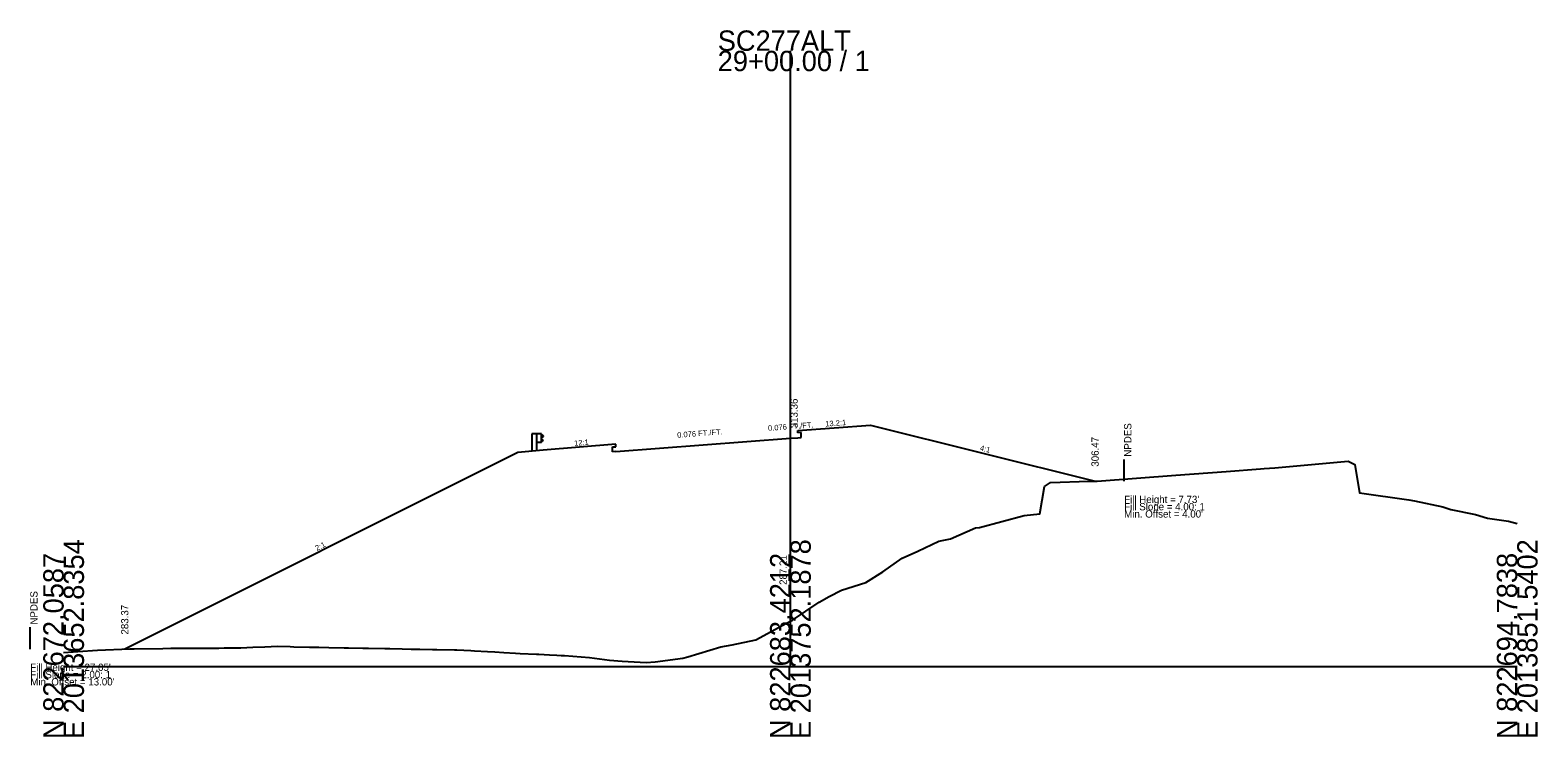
# Model space of a CAD drawing. Extents: x 205929 to 2357175, y -1785700 to 827636.
# Drawn here: x 2017415.6 to 2017623, y 827034.6 to 827131.8 of the extents above; entities that cross this region are included whole.
import ezdxf

# ---------------------------------------------------------------- set-up
doc = ezdxf.new("R2010")
doc.units = 0
for name, color, linetype in [('RD_GPK_XS_Cell', 7, 'Continuous'), ('RD_XS_Base', 7, 'Continuous'), ('RD_XS_EarthShd', 7, 'Continuous'), ('RD_XS_ExGround', 7, 'Continuous'), ('RD_XS_GR', 7, 'Continuous'), ('RD_XS_NPDES', 7, 'Continuous'), ('RD_XS_Pave', 7, 'Continuous'), ('RD_XS_TieSlope', 7, 'Continuous'), ('RD_XS_TX_Elev_EX', 7, 'Continuous'), ('RD_XS_TX_Elev_PR', 7, 'Continuous'), ('RD_XS_TX_ShdSlope', 7, 'Continuous'), ('RD_XS_TX_Slope', 7, 'Continuous'), ('RD_XS_TX_Warning', 7, 'Continuous')]:
    doc.layers.add(name, color=color, linetype=linetype)

msp = doc.modelspace()

# ---------------------------------------------------------------- linework, layer by layer
at = {"layer": 'RD_GPK_XS_Cell'}
for p, q in [((2017520.17, 827044.26), (2017520.17, 827128.92)), ((2017420.17, 827044.26), (2017520.17, 827044.26)), ((2017520.17, 827044.26), (2017620.17, 827044.26))]:
    msp.add_line(p, q, dxfattribs=at)
at = {"layer": 'RD_XS_Base'}
for p, q in [((2017496.17, 827073.8), (2017520.17, 827075.62)), ((2017520.17, 827075.62), (2017521.17, 827075.69))]:
    msp.add_line(p, q, dxfattribs=at)
at = {"layer": 'RD_XS_EarthShd'}
for p, q in [((2017521.17, 827076.69), (2017531.17, 827077.45)), ((2017486.17, 827073.97), (2017482.67, 827073.67)), ((2017496.17, 827074.8), (2017486.17, 827073.97))]:
    msp.add_line(p, q, dxfattribs=at)
at = {"layer": 'RD_XS_ExGround'}
msp.add_lwpolyline([(2017420.17, 827046.18), (2017424.14, 827046.43), (2017424.85, 827046.47), (2017429.29, 827046.66), (2017429.88, 827046.67), (2017433.81, 827046.72), (2017434.91, 827046.74), (2017438.32, 827046.74), (2017440.74, 827046.75), (2017441.05, 827046.76), (2017441.53, 827046.77), (2017442.28, 827046.79), (2017443.7, 827046.8), (2017444.57, 827046.82), (2017446.2, 827046.89), (2017447.85, 827046.95), (2017448.72, 827046.99), (2017449.57, 827047.02), (2017451.33, 827046.97), (2017451.84, 827046.96), (2017454, 827046.91), (2017455.3, 827046.89), (2017456.67, 827046.87), (2017458.77, 827046.81), (2017459.35, 827046.8), (2017461.32, 827046.76), (2017462.1, 827046.75), (2017464.36, 827046.71), (2017465.05, 827046.69), (2017466.76, 827046.66), (2017467.99, 827046.63), (2017469.16, 827046.61), (2017470.93, 827046.57), (2017471.54, 827046.56), (2017473.95, 827046.52), (2017474.28, 827046.52), (2017476.22, 827046.42), (2017476.7, 827046.39), (2017478.48, 827046.3), (2017479.52, 827046.24), (2017480.73, 827046.16), (2017482.34, 827046.08), (2017482.98, 827046.04), (2017485.23, 827045.95), (2017485.54, 827045.94), (2017487.01, 827045.86), (2017488.01, 827045.8), (2017488.64, 827045.76), (2017489.09, 827045.74), (2017492.52, 827045.48), (2017495.3, 827045.13), (2017497.03, 827044.98), (2017500.34, 827044.78), (2017501.55, 827044.86), (2017505.37, 827045.37), (2017506.07, 827045.55), (2017510.58, 827046.95), (2017512.15, 827047.24), (2017515.43, 827047.91), (2017519.61, 827050.22), (2017520.47, 827050.59), (2017524.13, 827053.08), (2017525.5, 827053.87), (2017527.22, 827054.75), (2017530.53, 827055.8), (2017532.91, 827057.28), (2017535.56, 827059.13), (2017537.68, 827060.11), (2017540.6, 827061.46), (2017542.19, 827061.79), (2017545.63, 827063.33), (2017546.2, 827063.37), (2017552.32, 827065.01), (2017554.49, 827065.22), (2017555.14, 827069.01), (2017555.97, 827069.56), (2017561.24, 827069.71), (2017561.99, 827069.72), (2017562.37, 827069.74), (2017573.2, 827070.55), (2017580.12, 827071.07), (2017584.87, 827071.42), (2017585.34, 827071.46), (2017586.82, 827071.57), (2017596.93, 827072.48), (2017597.82, 827072.04), (2017598.48, 827068.11), (2017605.26, 827067.14), (2017606.02, 827067.03), (2017609.94, 827066.2), (2017611.05, 827065.81), (2017614.45, 827065.14), (2017616.09, 827064.65), (2017618.97, 827064.23), (2017620.17, 827063.92)], dxfattribs=at)
at = {"layer": 'RD_XS_GR'}
for p, q in [((2017484.57, 827076.22), (2017484.57, 827073.83)), ((2017485.24, 827076.22), (2017484.57, 827076.22)), ((2017485.24, 827076.22), (2017485.24, 827073.89)), ((2017485.9, 827076.22), (2017485.24, 827076.22)), ((2017485.9, 827075.05), (2017485.9, 827076.22)), ((2017485.9, 827076.14), (2017486.17, 827075.94)), ((2017486.17, 827075.89), (2017485.9, 827075.69)), ((2017486.17, 827075.37), (2017485.9, 827075.57)), ((2017486.17, 827075.94), (2017486.17, 827075.89)), ((2017485.9, 827075.05), (2017485.24, 827075.05)), ((2017485.9, 827075.12), (2017486.17, 827075.32)), ((2017486.17, 827075.32), (2017486.17, 827075.37))]:
    msp.add_line(p, q, dxfattribs=at)
at = {"layer": 'RD_XS_NPDES'}
for p, q in [((2017566.09, 827069.72), (2017566.09, 827072.72)), ((2017415.58, 827046.63), (2017415.58, 827049.63))]:
    msp.add_line(p, q, dxfattribs=at)
at = {"layer": 'RD_XS_Pave'}
for p, q in [((2017521.17, 827076.36), (2017521.17, 827076.69)), ((2017521.67, 827076.4), (2017521.17, 827076.36)), ((2017521.17, 827075.69), (2017521.67, 827075.73)), ((2017521.67, 827075.73), (2017521.67, 827076.4)), ((2017495.67, 827074.43), (2017496.17, 827074.47)), ((2017495.67, 827073.76), (2017495.67, 827074.43)), ((2017496.17, 827073.8), (2017495.67, 827073.76)), ((2017496.17, 827074.47), (2017496.17, 827074.8))]:
    msp.add_line(p, q, dxfattribs=at)
at = {"layer": 'RD_XS_TieSlope'}
for p, q in [((2017531.17, 827077.45), (2017562.09, 827069.72)), ((2017482.67, 827073.67), (2017428.58, 827046.63))]:
    msp.add_line(p, q, dxfattribs=at)

# ---------------------------------------------------------------- texts
at = {"layer": 'RD_GPK_XS_Cell'}
for s, p in [('SC277ALT', (2017510.17, 827128.92)), ('29+00.00 / 1', (2017510.17, 827126.12))]:
    msp.add_text(s, height=2.8, dxfattribs=at).set_placement(p)
for s, p in [('E 2013652.8354', (2017422.97, 827034.26)), ('E 2013752.1878', (2017522.97, 827034.26)), ('E 2013851.5402', (2017622.97, 827034.26)), ('N 822672.0587', (2017420.17, 827034.26)), ('N 822683.4212', (2017520.17, 827034.26)), ('N 822694.7838', (2017620.17, 827034.26))]:
    msp.add_text(s, height=2.8, rotation=90, dxfattribs=at).set_placement(p)
at = {"layer": 'RD_XS_TX_Elev_EX'}
msp.add_text('287.21', height=1, rotation=90, dxfattribs=at).set_placement((2017519.67, 827055.46))
at = {"layer": 'RD_XS_TX_Elev_PR'}
for s, p in [(' 313.36', (2017521.17, 827076.62)), ('306.47', (2017562.59, 827071.72)), ('283.37', (2017429.08, 827048.63))]:
    msp.add_text(s, height=1, rotation=90, dxfattribs=at).set_placement(p)
at = {"layer": 'RD_XS_TX_ShdSlope'}
for s, rotation, p in [('13.2:1', 4.3347, (2017525, 827077.23)), ('12:1', 4.7636, (2017490.44, 827074.57))]:
    msp.add_text(s, height=0.75, rotation=rotation, dxfattribs=at).set_placement(p)
at = {"layer": 'RD_XS_TX_Slope'}
for s, rotation, p in [('0.076 FT./FT.', 4.3347, (2017517.12, 827076.64)), ('0.076 FT./FT.', 4.3347, (2017504.62, 827075.69)), ('4:1', 345.9638, (2017546.18, 827073.96)), ('2:1', 26.5651, (2017455.01, 827060.12))]:
    msp.add_text(s, height=0.75, rotation=rotation, dxfattribs=at).set_placement(p)
at = {"layer": 'RD_XS_TX_Warning'}
for p in [(2017567.09, 827072.72), (2017416.58, 827049.63)]:
    msp.add_text(' NPDES', height=1, rotation=90, dxfattribs=at).set_placement(p)
for s, p in [("Fill Height = 7.73' ", (2017566.09, 827066.72)), ('Fill Slope = 4.00: 1', (2017566.09, 827065.72)), ("Min. Offset = 4.00' ", (2017566.09, 827064.72)), ("Fill Height = 27.05' ", (2017415.58, 827043.63)), ('Fill Slope = 2.00: 1', (2017415.58, 827042.63)), ("Min. Offset = 13.00' ", (2017415.58, 827041.63))]:
    msp.add_text(s, height=1, dxfattribs=at).set_placement(p)

doc.saveas('drawing.dxf')
